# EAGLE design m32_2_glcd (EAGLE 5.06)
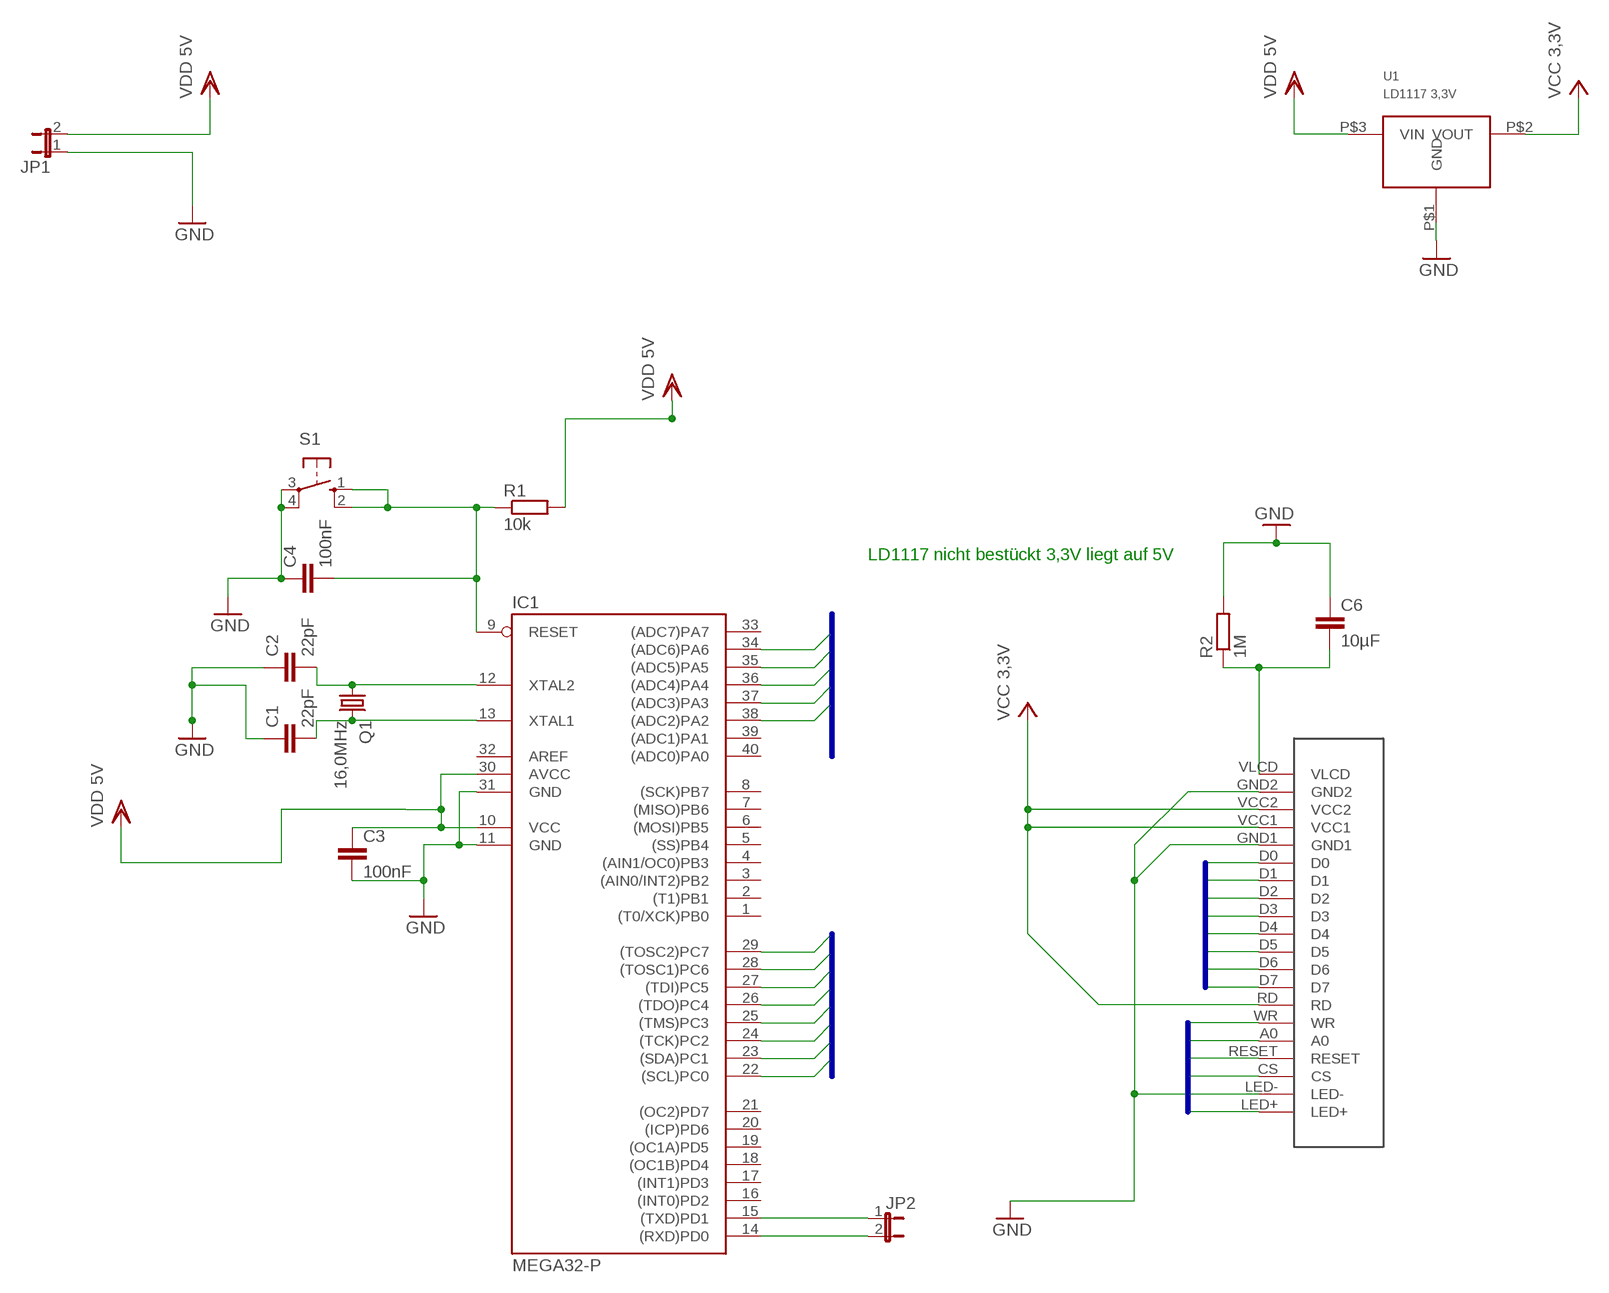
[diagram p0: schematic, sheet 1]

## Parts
C1  22pF  C-EU025-024X044  [C025-024X044]
C2  22pF  C-EU025-024X044  [C025-024X044]
C3  100nF  C-EU075-032X103  [C075-032X103]
C4  100nF  C-EU075-032X103  [C075-032X103]
C6  10µF  C-EU075-032X103  [C075-032X103]
IC1  MEGA32-P  [DIL40]
JP1  JP1E  [JP1]
JP2  JP1E  [JP1]
LCD1  DISPLAY_WOOLWORTH1  [DISPLAYWOOL2]
Q1  16,0MHz  CRYSTALHC49S  [HC49/S]
R1  10k  R-EU_0204/7  [0204/7]
R2  1M  R-EU_0204/7  [0204/7]
S1  10-XX  [B3F-10XX]
U1  LD1117 3,3V  LD1117  [DPAC]

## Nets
A0: IC1.35((ADC5)PA5) LCD1.A0
CS: IC1.37((ADC3)PA3) LCD1.CS
D0: IC1.22((SCL)PC0) LCD1.D0
D1: IC1.23((SDA)PC1) LCD1.D1
D2: IC1.24((TCK)PC2) LCD1.D2
D3: IC1.25((TMS)PC3) LCD1.D3
D4: IC1.26((TDO)PC4) LCD1.D4
D5: IC1.27((TDI)PC5) LCD1.D5
D6: IC1.28((TOSC1)PC6) LCD1.D6
D7: IC1.29((TOSC2)PC7) LCD1.D7
GND: C1.1 C2.1 C3.2 C4.1 C6.1 IC1.11(GND) IC1.31(GND) JP1.1 LCD1.GND1 LCD1.GND2 LCD1.LED- R2.2 S1.3(P) S1.4(P1) U1.P$1(GND)
HARDWARE_SPI: C4.2 IC1.9(RESET) R1.1 S1.1(S) S1.2(S1)
LCD_RESET: IC1.36((ADC4)PA4) LCD1.RESET
LED+: IC1.38((ADC2)PA2) LCD1.LED+
N$1: C2.2 IC1.12(XTAL2) Q1.1
N$2: C1.2 IC1.13(XTAL1) Q1.2
N$4: IC1.15((TXD)PD1) JP2.1
N$6: IC1.14((RXD)PD0) JP2.2
N$7: C6.2 LCD1.VLCD R2.1
VCC: LCD1.RD LCD1.VCC1 LCD1.VCC2 U1.P$2(VOUT) ; supply symbol labelled VCC 3,3V
VDD: C3.1 IC1.10(VCC) IC1.30(AVCC) JP1.2 R1.2 U1.P$3(VIN) ; supply symbol labelled VDD 5V
WR: IC1.34((ADC6)PA6) LCD1.WR
Unconnected: IC1.1((T0/XCK)PB0) IC1.2((T1)PB1) IC1.3((AIN0/INT2)PB2) IC1.4((AIN1/OC0)PB3) IC1.5((SS)PB4) IC1.6((MOSI)PB5) IC1.7((MISO)PB6) IC1.8((SCK)PB7) IC1.16((INT0)PD2) IC1.17((INT1)PD3) IC1.18((OC1B)PD4) IC1.19((OC1A)PD5) IC1.20((ICP)PD6) IC1.21((OC2)PD7) IC1.32(AREF) IC1.33((ADC7)PA7) IC1.39((ADC1)PA1) IC1.40((ADC0)PA0)

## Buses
LCD_DATA:D0,D1,D2,D3,D4,D5,D6,D7
LCD1_CTRL:LCD_RESET,A0,WR,CS,LED+

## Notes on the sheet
- LD1117 nicht bestückt 3,3V liegt auf 5V

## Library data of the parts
C1-C4 C6 = resistor:C-EU: CAPACITOR, European symbol
IC1 = atmel:MEGA32-P: MICROCONTROLLER 32 Kbytes FLASH 2 Kbytes SRAM 1 Kbytes EEPROM USART 8-channel 10 bit ADC Source: www.atmel.com .. doc2503.pdf
JP1 JP2 = jumper:JP1E: JUMPER
LCD1 = Display_woolworth:DISPLAY_WOOLWORTH1
Q1 = crystal:CRYSTAL: CRYSTAL
R1 R2 = resistor:R-EU_: RESISTOR, European symbol
S1 = switch-omron:10-XX: OMRON SWITCH
U1 = m0khz2:LD1117

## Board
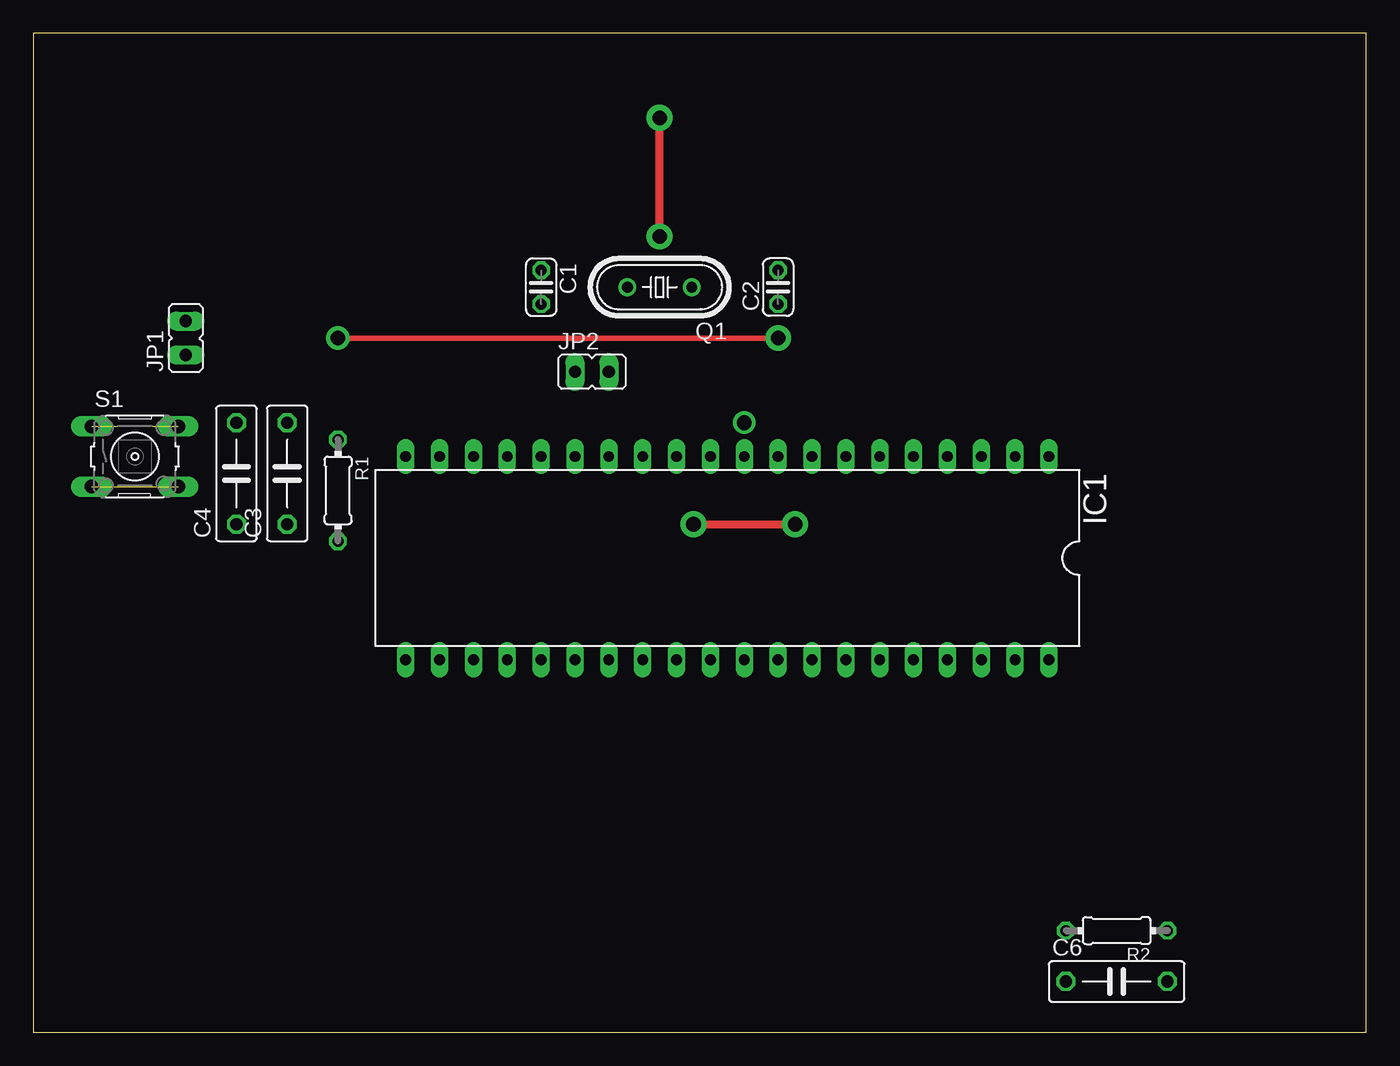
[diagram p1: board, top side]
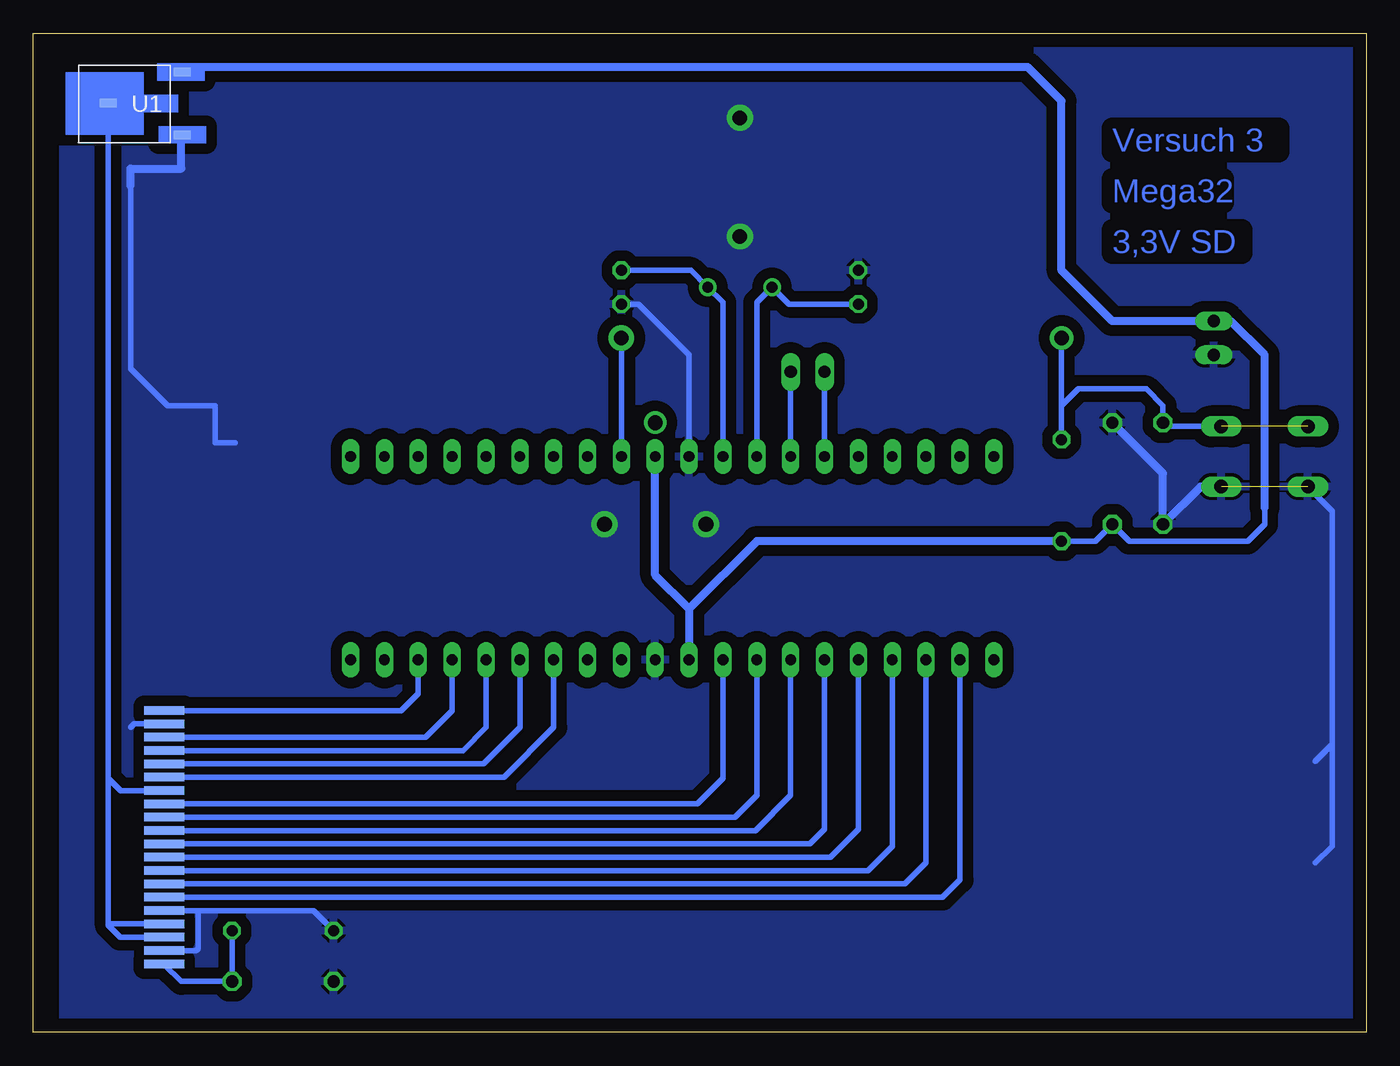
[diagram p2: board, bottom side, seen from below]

Size 100 x 74.92 mm. Coordinates in mm from the lower left corner, seen from the top.
Outline: 0,0 100,0 100,74.92 0,74.92 0,0
Copper layers (1*16): Top 0.035mm / dielectric 1.5mm / Bottom 0.035mm
Design rules "default *": minimum track width 10mil, minimum drill 24mil, track to track 8mil, track to pad 8mil, pad to pad 8mil, via to via 8mil, smd to smd 8mil, copper to edge 40mil, drill to drill 8mil, minimum pad ring 10mil, minimum via ring 8mil, stop-mask expansion 4mil, vias tented up to drill 0mil, thermal gap 10mil

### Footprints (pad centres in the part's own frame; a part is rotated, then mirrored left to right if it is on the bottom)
C025-024X044 = drill 0.813 octagon: 1 -1.27,0; 2 1.27,0
C075-032X103 = drill 0.914 octagon: 1 -3.81,0; 2 3.81,0
DIL40 = drill 0.813 long: 1 -24.13,-7.62; 2 -21.59,-7.62; 3 -19.05,-7.62; 4 -16.51,-7.62; 5 -13.97,-7.62; 6 -11.43,-7.62; 7 -8.89,-7.62; 8 -6.35,-7.62; 9 -3.81,-7.62; 10 -1.27,-7.62; 11 1.27,-7.62; 12 3.81,-7.62; 13 6.35,-7.62; 14 8.89,-7.62; 15 11.43,-7.62; 16 13.97,-7.62; 17 16.51,-7.62; 18 19.05,-7.62; 19 21.59,-7.62; 20 24.13,-7.62; 21 24.13,7.62; 22 21.59,7.62; 23 19.05,7.62; 24 16.51,7.62; 25 13.97,7.62; 26 11.43,7.62; 27 8.89,7.62; 28 6.35,7.62; 29 3.81,7.62; 30 1.27,7.62; 31 -1.27,7.62; 32 -3.81,7.62; 33 -6.35,7.62; 34 -8.89,7.62; 35 -11.43,7.62; 36 -13.97,7.62; 37 -16.51,7.62; 38 -19.05,7.62; 39 -21.59,7.62; 40 -24.13,7.62
JP1 = drill 0.914 long: 1 0,-1.27; 2 0,1.27
DISPLAYWOOL2 = smd 3 x 0.635: A0 0,-4; CS 0,-2; D0 0,-14; D1 0,-13; D2 0,-12; D3 0,-11; D4 0,-10; D5 0,-9; D6 0,-8; D7 0,-7; GND1 0,-15; GND2 0,-18; LED+ 0,0; LED- 0,-1; RD 0,-6; RESET 0,-3; VCC1 0,-16; VCC2 0,-17; VLCD 0,-19; WR 0,-5
HC49/S = drill 0.813 round: 1 -2.413,0; 2 2.413,0
0204/7 = drill 0.813 octagon: 1 -3.81,0; 2 3.81,0
B3F-10XX = drill 1.016 long: 1 -3.251,2.261; 2 3.251,2.261; 3 -3.251,-2.261; 4 3.251,-2.261
DPAC = smd 0.635 x 1.27: P$1 0,1.2; P$2 2.4,6.75; P$3 4.7,1.2

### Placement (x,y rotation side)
C1  38.1,55.88 270 top
C2  55.88,55.88 90 top
C3  19.05,41.91 90 top
C4  15.24,41.91 90 top
C6  81.28,3.81 0 top
IC1  52.07,35.56 180 top
JP1  11.43,52.07 0 top
JP2  41.91,49.53 270 top
LCD1  90.17,24.13 0 bottom
Q1  46.99,55.88 180 top
R1  22.86,40.64 270 top
R2  81.28,7.62 180 top
S1  7.62,43.18 0 top
U1  87.63,67.31 90 bottom

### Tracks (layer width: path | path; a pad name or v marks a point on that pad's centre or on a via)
A0
  Bottom 0.406: LCD1.A0 66.23,20.13 63.5,22.86 IC1.35
CS
  Bottom 0.406: LCD1.CS 70.58,22.13 68.58,24.13 IC1.37
D0
  Bottom 0.406: LCD1.D0 31.78,10.13 30.48,11.43 IC1.22
D1
  Bottom 0.406: LCD1.D1 34.59,11.13 33.02,12.7 IC1.23
D2
  Bottom 0.406: LCD1.D2 37.4,12.13 35.56,13.97 IC1.24
D3
  Bottom 0.406: LCD1.D3 40.21,13.13 38.1,15.24 IC1.25
D4
  Bottom 0.406: LCD1.D4 41.75,14.13 40.64,15.24 IC1.26
D5
  Bottom 0.406: LCD1.D5 45.83,15.13 43.18,17.78 IC1.27
D6
  Bottom 0.406: LCD1.D6 47.37,16.13 45.72,17.78 IC1.28
D7
  Bottom 0.406: LCD1.D7 50.18,17.13 48.26,19.05 IC1.29
GND  (via drill 1.1 pad 1.93)  (1 unrouted)
  Top 0.61: v49.53,38.1 v57.15,38.1 | v46.99,59.69 v46.99,68.58
  Bottom 0.406: 84.87,44.23 86.36,44.23 86.36,46.99 89.93,46.99 92.71,49.77 92.71,63.5 | C2.1 54.61,54.61 50.8,50.8 IC1.11 | S1.3 2.54,39.09 2.54,21.59 | 2.54,21.59 3.81,20.32 | 2.54,21.59 2.54,13.97 3.81,12.7 | 87.63,9.13 78.98,9.13 R2.2 | 87.63,9.13 LCD1.GND1 | LCD1.LED- 92.44,23.13 92.71,22.86 | LCD1.GND2 87.85,6.13 arc-90 87.63,6.35 87.63,9.13
  Bottom 0.61: U1.P$1 88.9,67.31 88.9,64.77 92.71,64.77 92.71,63.5 | S1.4 12.42,40.92 C4.1 15.24,41.91 C3.2
  pour Bottom (isolate 0.813): 0,74.93 97.79,74.93 97.79,0 0,0
HARDWARE_SPI  (via drill 1.1 pad 1.78)  (1 unrouted)
  Top 0.406: v22.86,52.07 v55.88,52.07
  Bottom 0.406: S1.2 15.24,45.44 C4.2 15.24,46.99 16.51,48.26 21.59,48.26 22.86,46.99 22.86,45.72 | 22.86,45.72 R1.1 | 22.86,45.72 v22.86,52.07 | v55.88,52.07 IC1.9
LCD_RESET
  Bottom 0.406: LCD1.RESET 67.77,21.13 66.04,22.86 IC1.36
LED+
  Bottom 0.406: LCD1.LED+ 72.39,24.13 71.12,25.4 IC1.38
N$1
  Bottom 0.406: C2.2 50.67,57.15 Q1.1 48.26,54.74 IC1.12
N$2
  Bottom 0.406: C1.2 43.31,54.61 Q1.2 45.72,54.74 IC1.13
N$4
  Bottom 0.406: IC1.15 JP2.1
N$6
  Bottom 0.406: IC1.14 JP2.2
N$7
  Bottom 0.406: R2.1 C6.2 88.9,3.81 90.17,5.08 LCD1.VLCD
N$39  (via drill 1.1 pad 1.93)
  other vias: 55.88,52.07
N$40  (via drill 1.1 pad 1.68)
  other vias: 53.34,45.72
VCC
  Bottom 0.406: 94.38,8.02 94.38,19.05 | 94.38,19.05 U1.P$2 | LCD1.VCC2 93.49,7.13 94.38,8.02 | LCD1.VCC1 94.27,8.13 94.38,8.02 | LCD1.RD 93.46,18.13 94.38,19.05
VDD
  Bottom 0.406: 88.45,72.39 U1.P$3 | R1.2 20.32,36.83 C3.1 17.78,36.83 8.89,36.83 7.62,38.1 7.62,39.37
  Bottom 0.61: 88.45,72.39 25.4,72.39 22.86,69.85 22.86,57.15 19.05,53.34 JP1.2 10.16,53.34 7.62,50.8 7.62,39.37 | 50.8,31.75 IC1.30 | 50.8,31.75 53.34,34.29 IC1.10 | R1.2 45.72,36.83 50.8,31.75
WR
  Bottom 0.406: LCD1.WR 64.69,19.13 60.96,22.86 IC1.34

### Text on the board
Bottom: Versuch 3 | Mega32 | 3,3V SD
